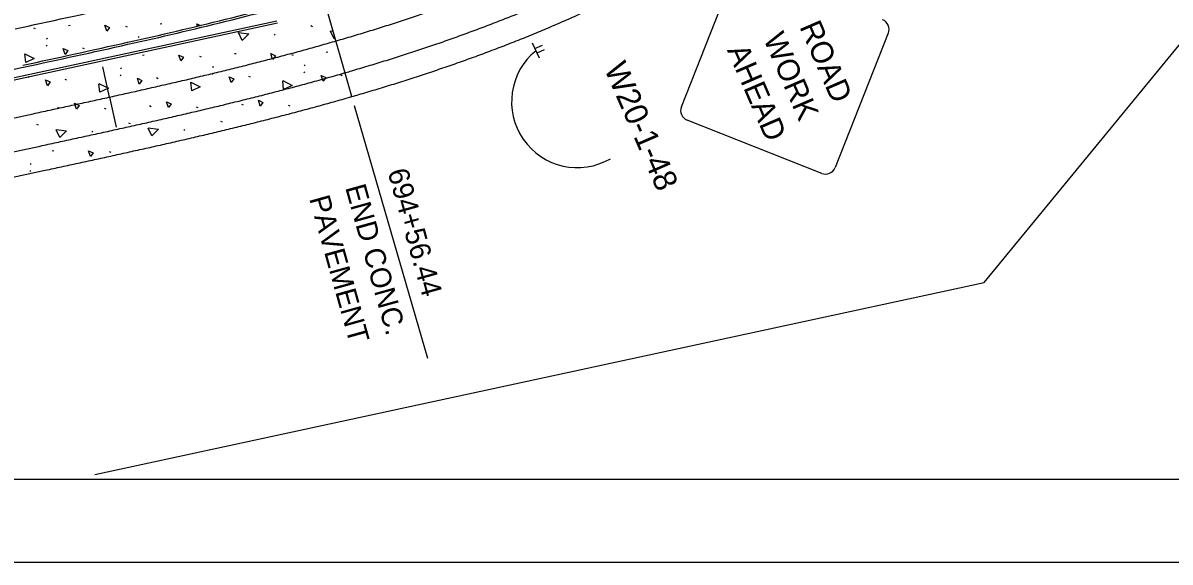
# Model space of a CAD drawing. Extents: x 0 to 1360, y 0 to 880.
# Drawn here: x 409.3 to 686.9, y 0 to 130.5 of the extents above; entities that cross this region are included whole.
import ezdxf

# ---------------------------------------------------------------- set-up
doc = ezdxf.new("R2010")
doc.units = 0
for name, color, linetype in [('Default', 7, 'Continuous'), ('MT_P_Traffic_Attenuator', 7, 'Continuous'), ('PV_X_Curb', 7, 'Continuous'), ('PV_X_EOP', 7, 'Continuous'), ('PV_X_Shoulder', 7, 'Continuous'), ('RD_X_Concrete_Pad', 7, 'Continuous'), ('RW_X_Fee_RW', 7, 'Continuous'), ('SH_Border', 7, 'Continuous'), ('SH_Cut_Line', 7, 'Continuous'), ('SN_P_Signs', 7, 'Continuous'), ('SN_P_Text', 7, 'Continuous')]:
    doc.layers.add(name, color=color, linetype=linetype)

# ---------------------------------------------------------------- blocks, each defined once
blk = doc.blocks.new('SGN2PP')
at = {"layer": 'SN_P_Signs'}
for p, q in [((0, 0.024), (-0.08, 0.024)), ((0, 0.08), (0, -0.08)), ((0, 0), (0, 0)), ((0, 0), (0, 0)), ((0, -0.024), (-0.08, -0.024))]:
    blk.add_line(p, q, dxfattribs=at)

msp = doc.modelspace()

# ---------------------------------------------------------------- linework, layer by layer
at = {"layer": 'Default'}
for p, q in [((411.89, 129.32), (412.29, 129.14)), ((420.7, 129.87), (420.31, 129.82)), ((434.12, 129.68), (434.53, 129.51)), ((442.94, 130.23), (442.54, 130.18)), ((470.34, 127.74), (470.08, 127.56)), ((478.96, 129.83), (479.36, 129.66)), ((415.15, 125.07), (414.88, 124.89)), ((415.22, 126.75), (414.96, 126.57)), ((437.46, 127.11), (437.19, 126.93)), ((423.73, 124.45), (424.13, 124.28)), ((438.63, 122.66), (438.23, 122.61)), ((452.04, 122.47), (452.45, 122.3)), ((460.86, 123.02), (460.46, 122.97)), ((474.28, 122.83), (474.68, 122.66)), ((483.1, 123.38), (482.7, 123.33)), ((430.26, 112.54), (428.64, 119.86)), ((433.14, 119.54), (432.88, 119.36)), ((455.38, 119.9), (455.11, 119.72)), ((477.62, 120.26), (477.35, 120.08)), ((410.83, 117.5), (410.56, 117.31)), ((419.41, 116.88), (419.81, 116.71)), ((433.07, 117.86), (432.8, 117.68)), ((441.65, 117.24), (442.05, 117.07)), ((455.3, 118.22), (455.04, 118.04)), ((463.89, 117.61), (464.29, 117.43)), ((477.54, 118.58), (477.28, 118.4)), ((486.13, 117.97), (486.53, 117.8)), ((430.26, 112.54), (431.87, 105.22)), ((158.95, 53.94), (411.75, 108.52)), ((417.7, 110.1), (418.1, 109.93)), ((428.99, 109.84), (429.39, 109.67)), ((439.94, 110.47), (440.34, 110.29)), ((451.22, 110.21), (451.63, 110.03)), ((462.18, 110.83), (462.58, 110.66)), ((473.46, 110.57), (473.86, 110.4)), ((507.3, 49.29), (489.57, 110.45)), ((412.62, 105.98), (413.02, 105.81)), ((434.86, 106.34), (435.26, 106.17)), ((457.09, 106.7), (457.5, 106.53)), ((426.23, 104.25), (425.97, 104.07)), ((448.47, 104.61), (448.21, 104.43)), ((337.24, 84.25), (413.44, 100.7)), ((416.76, 99.53), (416.36, 99.48)), ((430.18, 99.34), (430.58, 99.17)), ((411.2, 94.73), (410.94, 94.55)), ((411.27, 96.41), (411.01, 96.23))]:
    msp.add_line(p, q, dxfattribs=at)
for points in [[(429.1, 129.91), (430.22, 129.39), (429.57, 128.49), (429.1, 129.91)], [(451.34, 130.27), (452.22, 129.86)], [(451.53, 129.69), (451.34, 130.27)], [(461.43, 128.19), (463.98, 127.87), (462.36, 126.26), (461.45, 128.14)], [(483.67, 128.55), (484.34, 128.47)], [(484.82, 126.84), (484.6, 126.62), (483.69, 128.51)], [(409.77, 123.03), (412.05, 121.87), (409.98, 120.9), (409.77, 122.98)], [(419.07, 124.29), (420.19, 123.78), (419.54, 122.88), (419.07, 124.29)], [(447.02, 122.7), (448.14, 122.18), (447.49, 121.28), (447.02, 122.7)], [(469.26, 123.06), (470.38, 122.54), (469.73, 121.64), (469.26, 123.06)], [(414.75, 116.72), (415.87, 116.2), (415.22, 115.3), (414.75, 116.72)], [(436.99, 117.08), (438.11, 116.56), (437.46, 115.67), (436.99, 117.08)], [(459.23, 117.44), (460.35, 116.93), (459.69, 116.03), (459.23, 117.44)], [(481.47, 117.8), (482.58, 117.29), (481.93, 116.39), (481.47, 117.8)], [(427.69, 115.82), (429.97, 114.66), (427.9, 113.69), (427.69, 115.77)], [(449.93, 116.18), (452.21, 115.02), (450.14, 114.05), (449.93, 116.13)], [(472.16, 116.54), (474.45, 115.38), (472.38, 114.41), (472.17, 116.5)], [(421.79, 111.05), (422.91, 110.53), (422.26, 109.64), (421.79, 111.05)], [(444.03, 111.41), (445.15, 110.9), (444.5, 110), (444.03, 111.41)], [(466.27, 111.77), (467.39, 111.26), (466.74, 110.36), (466.27, 111.77)], [(417.33, 104.69), (419.87, 104.38), (418.26, 102.77), (417.35, 104.65)], [(439.57, 105.06), (442.11, 104.75), (440.5, 103.13), (439.58, 105.02)], [(425.16, 99.57), (426.27, 99.05), (425.62, 98.15), (425.16, 99.57)]]:
    msp.add_lwpolyline(points, dxfattribs=at)
msp.add_arc((543.47, 111.39), 15.92, 128.9777, 300.1796, dxfattribs=at)
for points in [[(407.38, 129.06), (432.62, 134.58), (456.13, 140.1), (479.83, 146.42), (503.62, 153.93), (526.94, 163.59), (549.22, 175.79)], [(411.75, 108.52), (413.73, 108.94), (415.71, 109.37), (417.69, 109.8), (419.67, 110.23), (421.66, 110.66), (423.64, 111.09), (425.62, 111.52), (427.6, 111.96), (429.58, 112.39), (431.56, 112.83), (433.54, 113.27), (435.51, 113.71), (437.49, 114.15), (439.47, 114.6), (441.45, 115.04), (443.42, 115.5), (445.4, 115.95), (447.37, 116.41), (449.35, 116.87), (451.32, 117.34), (453.29, 117.81), (455.26, 118.28), (457.23, 118.76), (459.2, 119.24), (461.17, 119.73), (463.13, 120.22), (465.1, 120.72), (467.06, 121.22), (469.02, 121.73), (470.99, 122.24), (472.94, 122.76), (474.9, 123.29), (476.86, 123.82), (478.81, 124.36), (480.76, 124.9), (482.71, 125.46), (484.66, 126.02), (486.61, 126.58), (488.55, 127.16), (490.5, 127.74), (492.43, 128.33), (494.37, 128.92), (496.31, 129.53), (498.24, 130.14), (500.17, 130.77), (502.09, 131.4), (504.02, 132.04), (505.94, 132.69), (507.85, 133.34), (509.77, 134.01), (511.68, 134.69), (513.59, 135.38), (515.49, 136.07), (517.39, 136.78), (519.29, 137.5), (521.18, 138.22), (523.06, 138.96), (524.95, 139.71), (526.83, 140.47), (528.7, 141.24), (530.57, 142.03), (532.44, 142.82), (534.3, 143.63), (536.15, 144.44), (538, 145.27), (539.85, 146.11), (541.68, 146.97), (543.52, 147.83), (545.34, 148.71), (547.16, 149.6), (548.98, 150.51), (550.79, 151.42), (552.59, 152.35), (554.38, 153.3)], [(413.44, 100.7), (415.42, 101.12), (417.4, 101.55), (419.39, 101.98), (421.37, 102.41), (423.35, 102.84), (425.34, 103.27), (427.32, 103.71), (429.31, 104.14), (431.3, 104.58), (433.28, 105.02), (435.27, 105.46), (437.26, 105.9), (439.25, 106.34), (441.23, 106.79), (443.22, 107.24), (445.21, 107.7), (447.2, 108.16), (449.19, 108.62), (451.18, 109.08), (453.16, 109.55), (455.15, 110.03), (457.14, 110.5), (459.13, 110.99), (461.11, 111.47), (463.1, 111.96), (465.09, 112.46), (467.07, 112.96), (469.06, 113.47), (471.04, 113.99), (473.03, 114.51), (475.01, 115.03), (476.99, 115.56), (478.97, 116.1), (480.95, 116.65), (482.93, 117.2), (484.91, 117.76), (486.88, 118.33), (487.25, 118.44)]]:
    msp.add_spline(points, degree=3, dxfattribs=at)
at = {"layer": 'PV_X_Curb'}
for p, q in [((244.24, 82.07), (470.75, 130.97)), ((244.34, 81.58), (470.86, 130.49)), ((294.88, 92.49), (470.86, 130.49)), ((244.01, 84.07), (409.38, 119.77)), ((409.38, 119.77), (409.41, 119.77))]:
    msp.add_line(p, q, dxfattribs=at)
for points in [[(409.3, 120.26), (434.61, 125.8), (458.32, 131.37), (482.34, 137.78), (506.71, 145.47), (530.83, 155.46), (541.98, 161.57)], [(409.3, 120.26), (434.61, 125.8), (458.32, 131.37), (482.34, 137.78), (506.71, 145.47), (530.83, 155.46), (541.98, 161.57)], [(409.41, 119.77), (434.72, 125.31), (458.44, 130.89), (482.48, 137.3), (506.88, 145), (531.05, 155.01), (542.22, 161.13)]]:
    msp.add_spline(points, degree=3, dxfattribs=at)
at = {"layer": 'PV_X_EOP'}
msp.add_spline([(487.4, 118.48), (488.86, 118.9), (490.83, 119.49), (492.81, 120.08), (494.78, 120.68), (496.75, 121.28), (498.71, 121.9), (500.68, 122.52), (502.64, 123.16), (504.6, 123.8), (506.56, 124.45), (508.52, 125.11), (510.47, 125.78), (512.42, 126.46), (514.37, 127.15), (516.32, 127.86), (518.26, 128.57), (520.2, 129.29), (522.14, 130.02), (524.07, 130.77), (526, 131.52), (527.93, 132.29), (529.85, 133.07), (531.77, 133.85), (533.68, 134.66), (535.59, 135.47), (537.5, 136.3), (539.4, 137.13), (541.3, 137.98), (543.19, 138.85), (545.08, 139.72), (546.96, 140.61), (548.84, 141.51), (550.71, 142.43), (552.57, 143.36), (554.43, 144.3), (556.28, 145.26), (558.1, 146.21)], degree=3, dxfattribs=at)
at = {"layer": 'PV_X_Shoulder'}
msp.add_spline([(488.92, 112.67), (490.55, 113.15), (492.54, 113.74), (494.54, 114.33), (496.53, 114.94), (498.53, 115.55), (500.52, 116.18), (502.51, 116.81), (504.5, 117.45), (506.48, 118.1), (508.47, 118.76), (510.45, 119.43), (512.43, 120.11), (514.41, 120.8), (516.39, 121.5), (518.37, 122.22), (520.34, 122.94), (522.31, 123.67), (524.28, 124.42), (526.24, 125.17), (528.2, 125.94), (530.16, 126.72), (532.12, 127.51), (534.07, 128.31), (536.02, 129.13), (537.96, 129.96), (539.9, 130.8), (541.84, 131.65), (543.77, 132.52), (545.7, 133.4), (547.62, 134.29), (549.54, 135.2), (551.45, 136.12), (553.36, 137.05), (555.27, 138), (557.16, 138.96), (559.05, 139.94), (560.89, 140.9)], degree=3, dxfattribs=at)
at = {"layer": 'RD_X_Concrete_Pad'}
for p, q in [((488.92, 112.67), (482.8, 133.8)), ((338.51, 78.38), (414.7, 94.83))]:
    msp.add_line(p, q, dxfattribs=at)
msp.add_spline([(414.7, 94.83), (416.69, 95.26), (418.67, 95.69), (420.65, 96.12), (422.64, 96.55), (424.63, 96.98), (426.62, 97.41), (428.61, 97.84), (430.6, 98.28), (432.59, 98.72), (434.58, 99.16), (436.57, 99.6), (438.57, 100.04), (440.56, 100.49), (442.56, 100.94), (444.55, 101.39), (446.55, 101.85), (448.55, 102.31), (450.55, 102.77), (452.55, 103.24), (454.55, 103.71), (456.55, 104.19), (458.55, 104.67), (460.55, 105.16), (462.55, 105.65), (464.55, 106.14), (466.55, 106.64), (468.55, 107.15), (470.55, 107.66), (472.55, 108.18), (474.56, 108.7), (476.56, 109.24), (478.56, 109.77), (480.56, 110.32), (482.56, 110.87), (484.55, 111.43), (486.55, 111.99), (488.55, 112.57), (488.92, 112.67)], degree=3, dxfattribs=at)
msp.add_spline([(414.7, 94.83), (416.69, 95.26), (418.67, 95.69), (420.65, 96.12), (422.64, 96.55), (424.63, 96.98), (426.62, 97.41), (428.61, 97.84), (430.6, 98.28), (432.59, 98.72), (434.58, 99.16), (436.57, 99.6), (438.57, 100.04), (440.56, 100.49), (442.56, 100.94), (444.55, 101.39), (446.55, 101.85), (448.55, 102.31), (450.55, 102.77), (452.55, 103.24), (454.55, 103.71), (456.55, 104.19), (458.55, 104.67), (460.55, 105.16), (462.55, 105.65), (464.55, 106.14), (466.55, 106.64), (468.55, 107.15), (470.55, 107.66), (472.55, 108.18), (474.56, 108.7), (476.56, 109.24), (478.56, 109.77), (480.56, 110.32), (482.56, 110.87), (484.55, 111.43), (486.55, 111.99), (488.55, 112.57), (488.92, 112.67)], degree=3, dxfattribs=at)
at = {"layer": 'RW_X_Fee_RW'}
for p, q in [((641.93, 67.68), (948.28, 440.99)), ((426.67, 21.21), (641.93, 67.68))]:
    msp.add_line(p, q, dxfattribs=at)
at = {"layer": 'SH_Border'}
msp.add_lwpolyline([(60, 860), (1340, 860), (1340, 20), (60, 20)], close=True, dxfattribs=at)
at = {"layer": 'SH_Cut_Line'}
msp.add_lwpolyline([(0, 0), (1360, 0), (1360, 880), (0, 880)], close=True, dxfattribs=at)
at = {"layer": 'SN_P_Signs'}
for points in [[(568.64, 110.2), (581.51, 142.74)], [(618.71, 128.03), (605.83, 95.48)], [(602.59, 94.08), (570.04, 106.95)]]:
    msp.add_lwpolyline(points, dxfattribs=at)
for centre, start, end in [((616.39, 128.95), 338.4154, 68.4154), ((570.96, 109.28), 158.4154, 248.4154), ((603.51, 96.4), 248.4154, 338.4154)]:
    msp.add_arc(centre, 2.5, start, end, dxfattribs=at)

# ---------------------------------------------------------------- block references
at = {"layer": 'MT_P_Traffic_Attenuator', "xscale": 25.000000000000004, "yscale": 24.999999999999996, "rotation": -155.78558369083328}
msp.add_blockref('SGN2PP', (533.45, 123.77), dxfattribs=at)

# ---------------------------------------------------------------- texts
at = {"layer": 'Default'}
for s, p in [('694+56.44', (497.5, 94.51)), ('END CONC.', (487.25, 90.68)), ('PAVEMENT', (478.54, 87.99))]:
    msp.add_text(s, height=5, rotation=285.5775, dxfattribs=at).set_placement(p)
at = {"layer": 'SN_P_Signs'}
for s, p in [('ROAD', (597.14, 129.58)), ('WORK', (588.37, 126.74)), ('AHEAD', (579.62, 123.9))]:
    msp.add_text(s, height=5.331, rotation=293.4154, dxfattribs=at).set_placement(p)
at = {"layer": 'SN_P_Text'}
msp.add_text('W20-1-48', height=5.6, rotation=293.4154, dxfattribs=at).set_placement((549.86, 119.51))

doc.saveas('drawing.dxf')
